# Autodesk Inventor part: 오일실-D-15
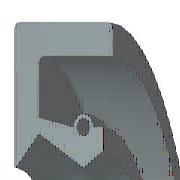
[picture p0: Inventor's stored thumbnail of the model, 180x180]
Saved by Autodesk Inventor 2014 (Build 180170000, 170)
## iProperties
IsCustomPart: 0
Company: 한국ATC센터
Created: 2014-12
Part Number: 오일실-D-15
Material: 고무
Description: 오일-실
Document SubType Name: Modeling
Standard: KS B 2804
Designer: KYOUNG IL JANG
Standards Organization: KS
Language: ko-KR
Size Designation: D - 15 30 7
Categories: <MemberInstance><Categories><Category DisplayName="샤프트 부품" InternalName="7f7aeb1f-a693-4053-b835-cee3144e0d98" Mnemonic="SHFT"><Category DisplayName="실링" Intern
Density: 0.93 g/cm^3
Mass: 1.95008 g
Surface Area: 27.8517 cm^2
Volume: 2.09686 cm^3
Appearance: 고무 - 파란색 - 버전 1.1
Author: KYOUNG IL JANG
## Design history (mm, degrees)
revolve "본체" stored, may be unused: angle "d17" = 90 deg
revolve "스프링1" stored, may be unused: angle "d18" = 90 deg
body "Solid1"
sketch "스케치1"
  geometry: L1 (0, 15)-(7, 15); L2 (7, 13.25)-(1.75, 13.25); L3 (1.75, 9.25)-(4.9, 7.5); L4 (4.9, 7.5)-(0, 7.5); L5 (0, 0)-(9.586, 0) reference; L6 (4.9, 7.5)-(6.3, 8.375); L7 (0, 18)-(0, -3) reference; L8 (-1.941, 0)-(11.507, 0) reference; L9 (4.2, 9.6)-(1.75, 10.09); L10 (1.75, 10.09)-(1.75, 13.25); L11 (0, 15)-(0, 7.588); L12 (4.9, 7.5)-(0, 7.5); L13 (1.75, 9.25)-(0.152, 7.528); L14 (7, 15)-(7, 13.25); L15 (5.6, 9.6)-(6.3, 9.6); L16 (6.3, 9.6)-(6.3, 8.375); C1 r 0.455 at (4.9, 9.6); A1 r 0.7 centre (4.9, 9.6) between (5.6, 9.6) and (4.2, 9.6); A2 r 0.088 centre (0.088, 7.588) between (0, 7.588) and (0.152, 7.528); 1 further point
  constraints: 28 end point, 5 horizontal alignment, 5 point on line, 4 point on circle, 4 vertical alignment, 3 centre point, 3 tangent, 2 collinear, 2 horizontal, 2 perpendicular, 1 coincident, 1 parallel
  dimensions: "d0" = 30 diameter of L1 L5 (= SD2); "d1" = 1.75 distance of L1.end L2.start (= SD); "d2" = 0.91 diameter of C1 (= SPDI); "d3" = 1.4 diameter of A1 (= SPDA); "d4" = 15 diameter of L3.end L5 (= NND); "d5" = 18.5 diameter of L3.start L5 (= TKDM); "d7" = 20.18 diameter of L9.end L5 (= TKDM + 0.24 x SWDT); "d8" = 1.75 distance between parallel lines of L11 L10 (= SD); "d9" = 4.9 distance from line of L11 C1.centre (= SPDST); "d10" = 19.2 diameter of C1.centre L5 (= HLDM); "d11" = 0.0875 radius of A2 (= 0.25 x LAB); "d12" = 6.3 distance between parallel lines of L11 L16 (= SDI); "d13" = 16.75 diameter of L6.end L5 (= ABDM); "d14" = 7 distance from line of L11 L1.end (= SWDT)
fillet "모깎기1" dims "d6" = 0.3 (= RR)
other parameters: "SD2" = 30 [user parameter; used in 1 equation term], "SWDT" = 7 [user parameter; used in 2 equation terms], "RR" = 0.3 [user parameter; used in 1 equation term], "SD" = 1.75 [user parameter; used in 2 equation terms], "NND" = 15 [user parameter; used in 1 equation term], "SPDA" = 1.4 [user parameter; used in 1 equation term], "SPDI" = 0.91 [user parameter; used in 1 equation term], "TKDM" = 18.5 [user parameter; used in 2 equation terms], "HLDM" = 19.2 [user parameter; used in 1 equation term], "ABDM" = 16.75 [user parameter; used in 1 equation term], "SDI" = 6.3 [user parameter; used in 1 equation term], "SPDST" = 4.9 [user parameter; used in 1 equation term], "LAB" = 0.35 [user parameter; used in 1 equation term], "d15" = 0, "d16" = 0, "d19" = 0
